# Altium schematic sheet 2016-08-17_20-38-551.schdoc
size 778 x 358 mm; SheetNumber: 1; SheetTotal: 1
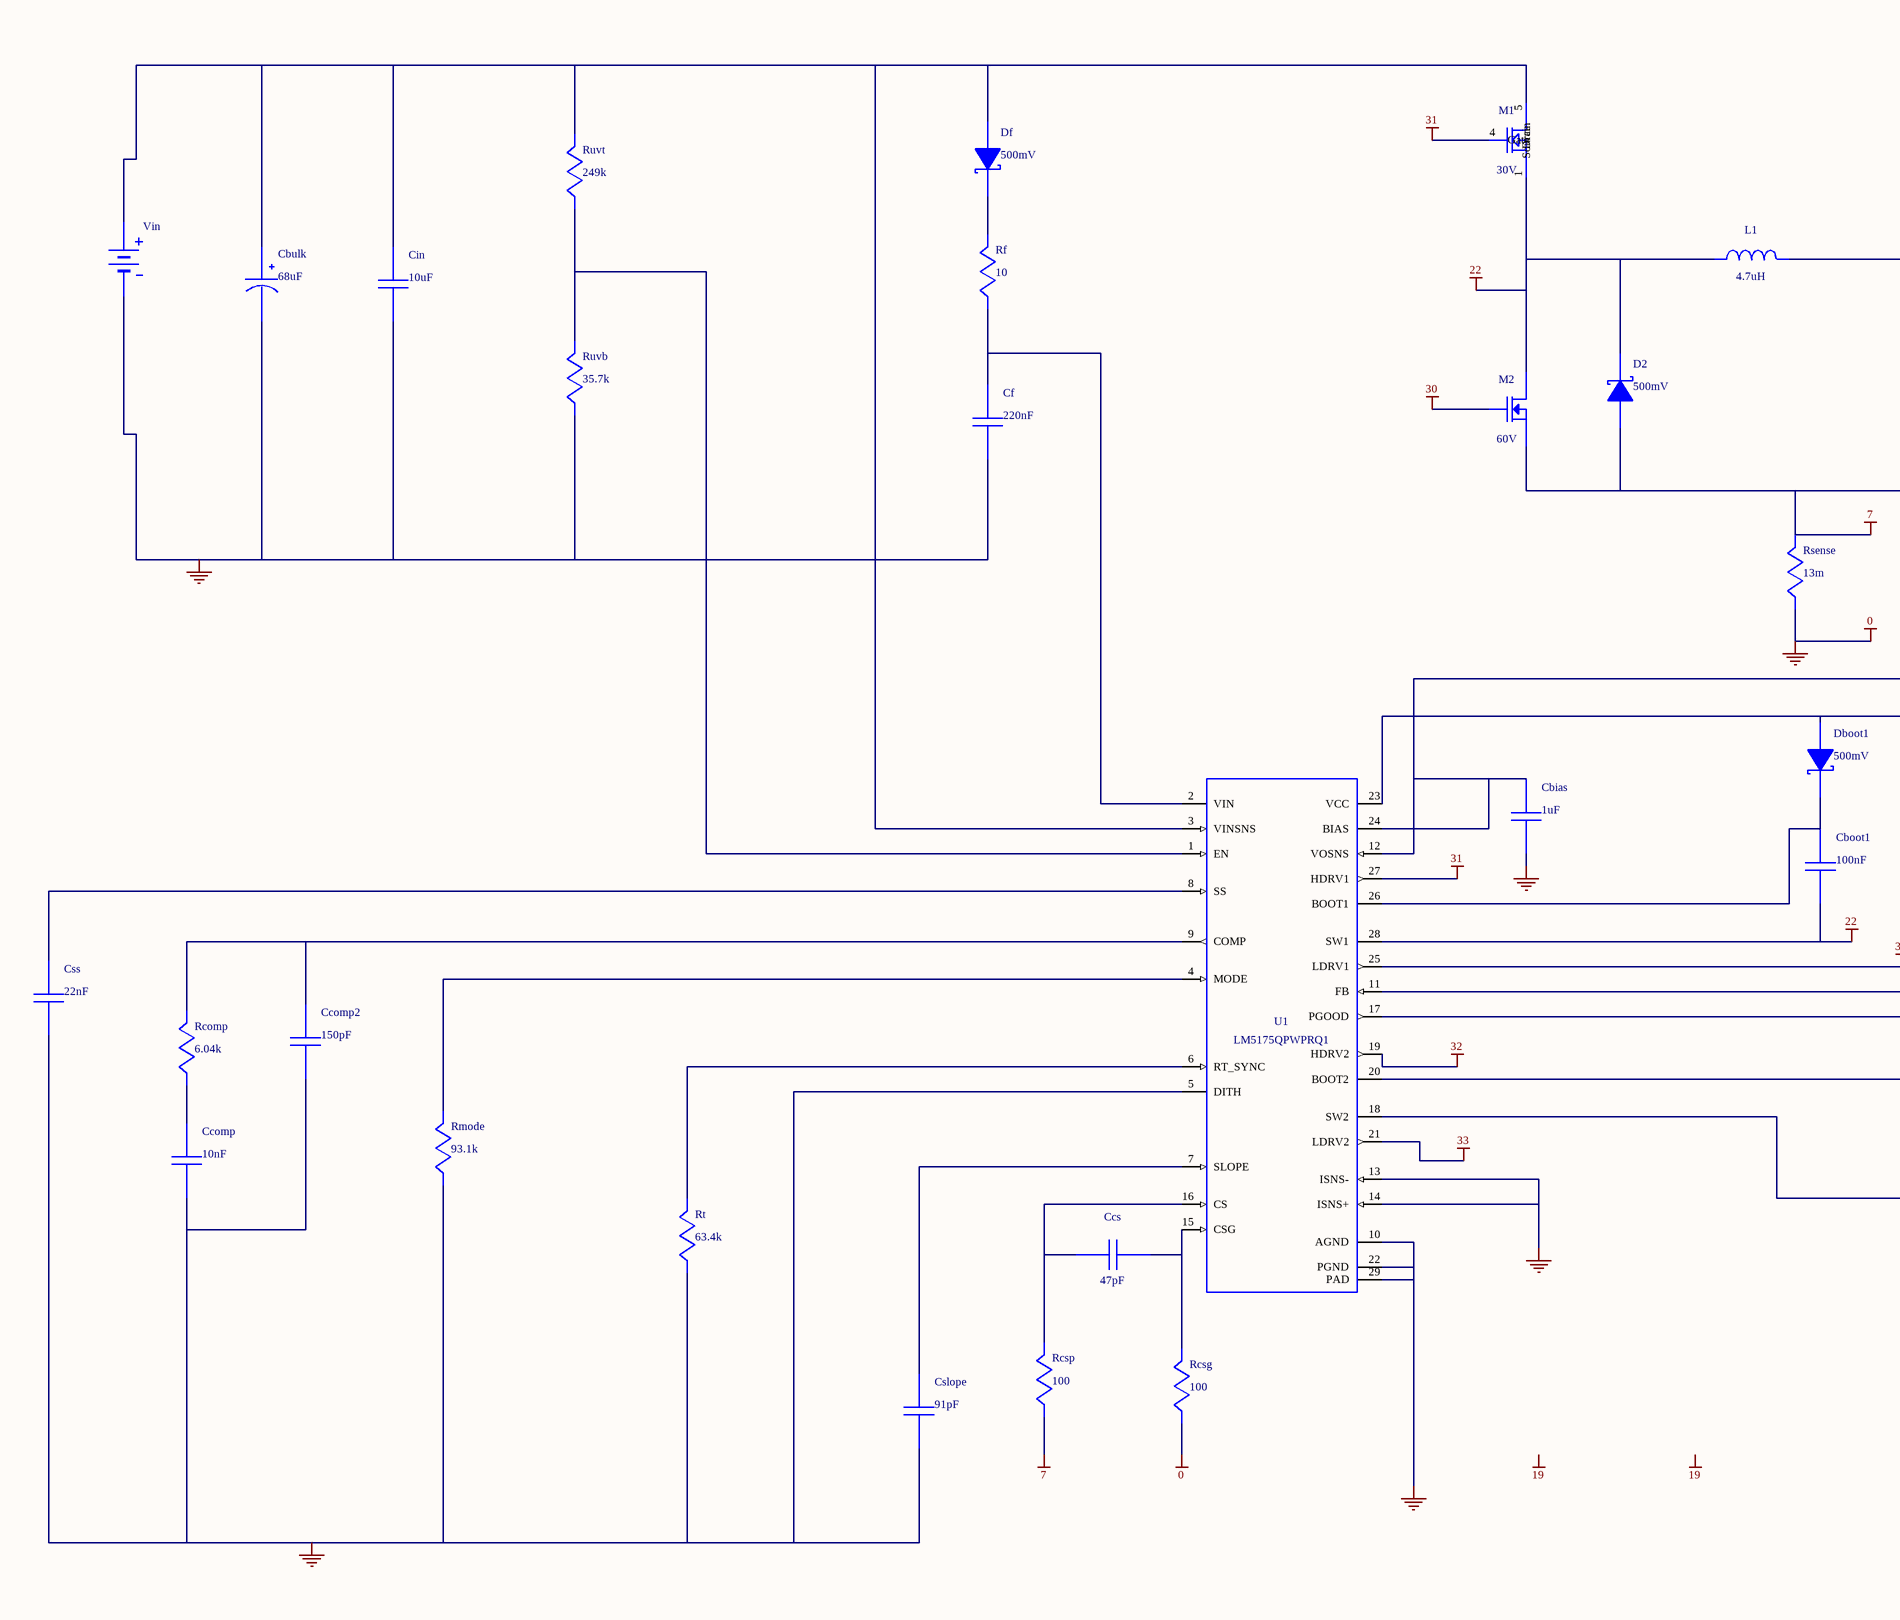
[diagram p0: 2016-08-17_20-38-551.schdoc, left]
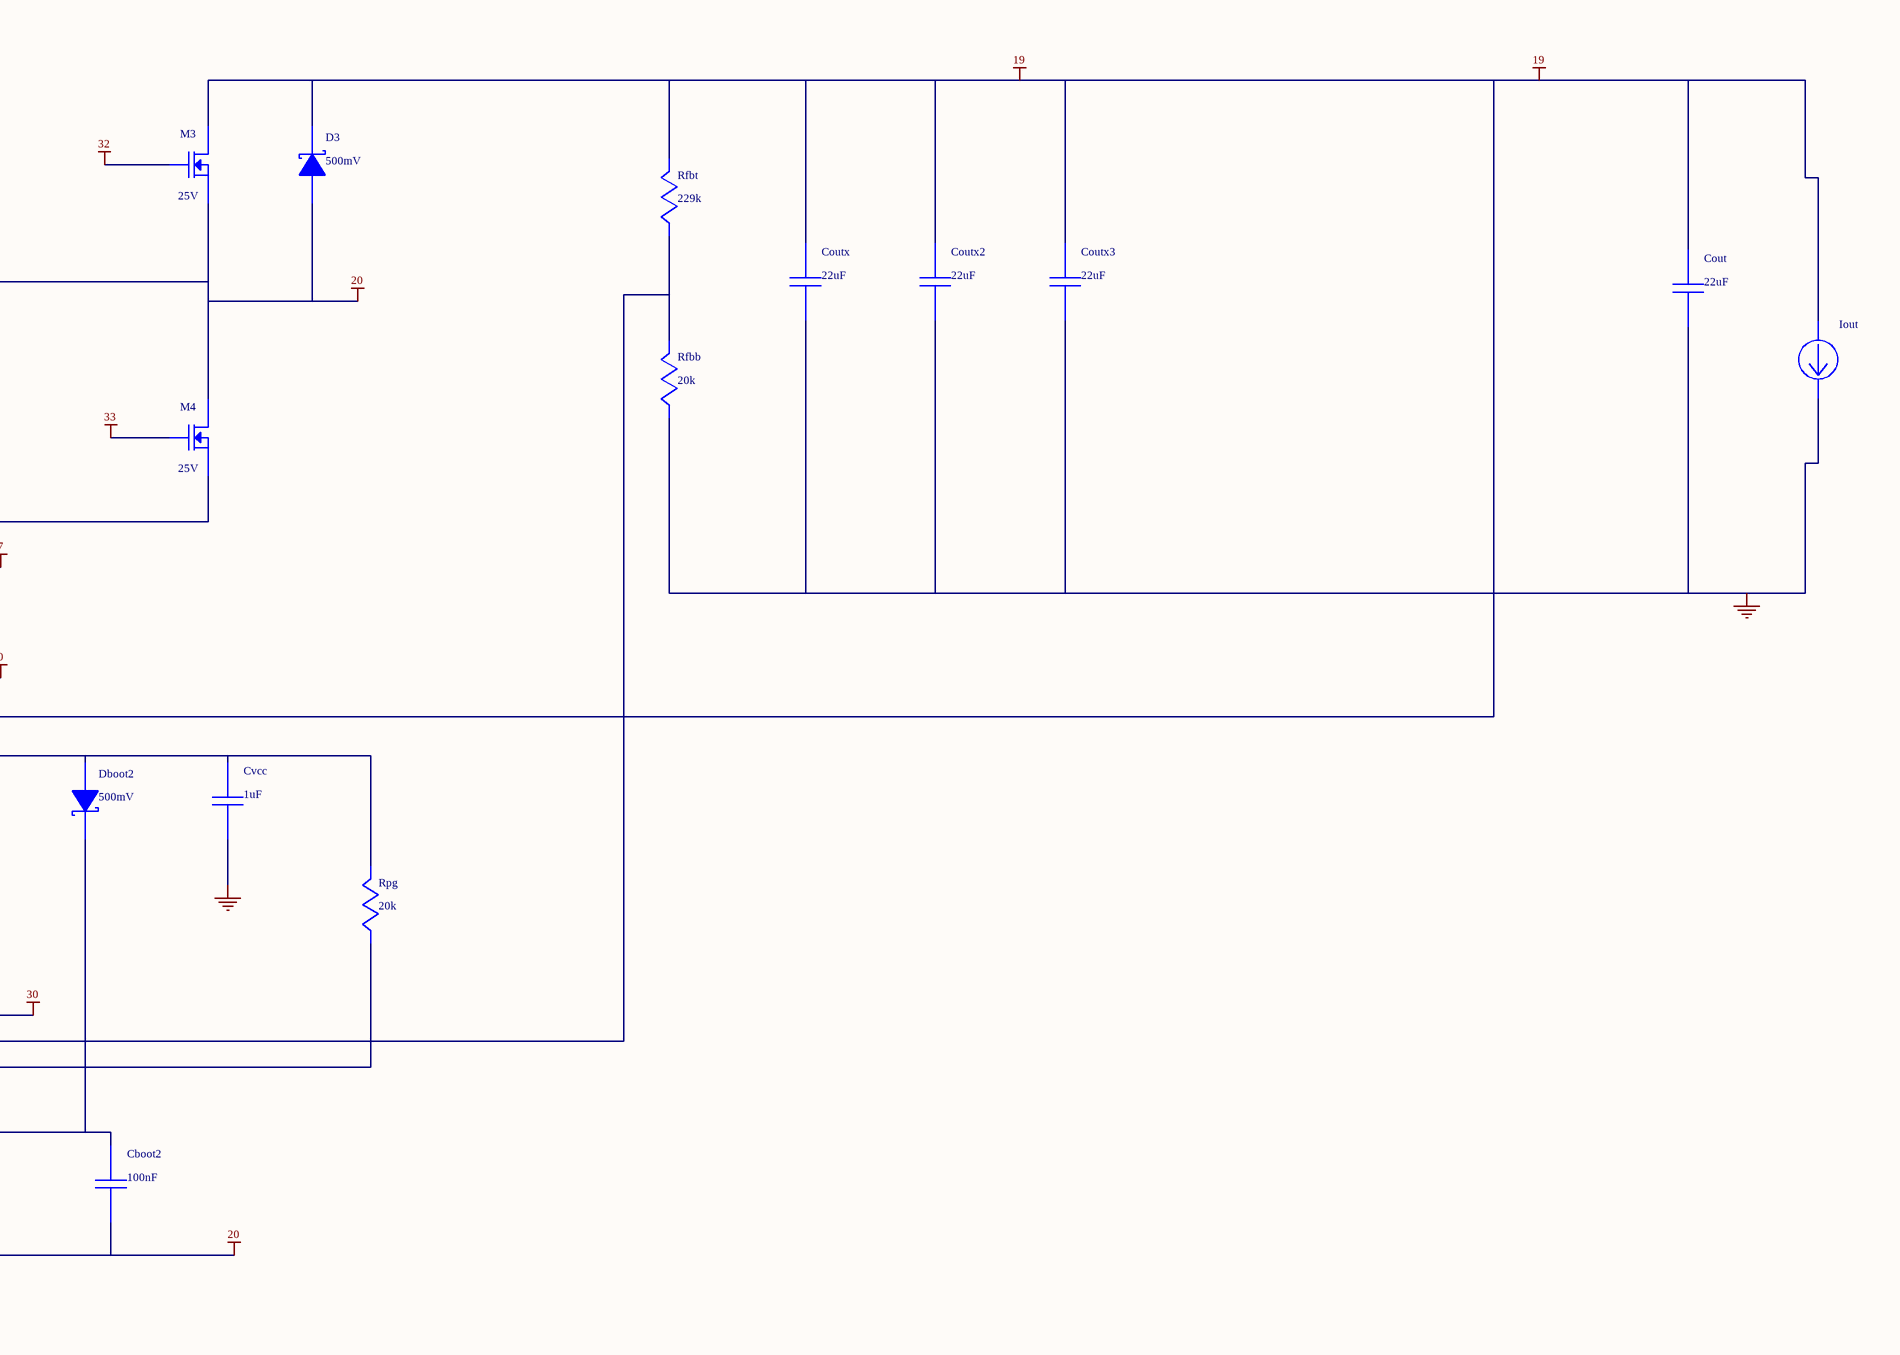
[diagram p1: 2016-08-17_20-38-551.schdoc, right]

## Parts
Cbias  value 1uF  (hidden comment: GRM188R61C105KA93D)
Cboot1  value 100nF  (hidden comment: C0603C104K3RACTU)
Cboot2  value 100nF  (hidden comment: C0603C104K3RACTU)
Cbulk  value 68uF  (hidden comment: UUD1E680MCL1GS)
Ccomp  value 10nF  (hidden comment: CC0805KRX7R9BB103)
Ccomp2  value 150pF  (hidden comment: C2012C0G1H151J)
Ccs  value 47pF  (hidden comment: 06035A470JAT2A)
Cf  value 220nF  (hidden comment: C0805C224K5RACTU)
Cin  value 10uF  (hidden comment: GRM32ER7YA106KA12L)
Cout  value 22uF  (hidden comment: GRM32ER61C226ME20L)
Coutx  value 22uF  (hidden comment: C3216JB1E226M)
Coutx2  value 22uF  (hidden comment: C3216JB1E226M)
Coutx3  value 22uF  (hidden comment: C3216JB1E226M)
Cslope  value 91pF  (hidden comment: CL10C910JB8NCNC)
Css  value 22nF  (hidden comment: C0603C223K3RACTU)
Cvcc  value 1uF  (hidden comment: GRM188R61C105KA93D)
D2  value 500mV  (hidden comment: CD214A-B130LF)
D3  value 500mV  (hidden comment: SS12-E3/61T)
Dboot1  value 500mV  (hidden comment: CD214A-B130LF)
Dboot2  value 500mV  (hidden comment: CD214A-B130LF)
Df  value 500mV  (hidden comment: CD214A-B130LF)
Iout  WB_CURRENT_LOAD  (value not drawn)
L1  value 4.7uH  (hidden comment: SDR0805-4R7ML)
M1  value 30V  (hidden comment: CSD17551Q3A)
M2  value 60V  (hidden comment: CSD18537NQ5A)
M3  value 25V  (hidden comment: CSD16323Q3)
M4  value 25V  (hidden comment: CSD16323Q3)
Rcomp  value 6.04k  (hidden comment: CRCW04026K04FKED)
Rcsg  value 100  (hidden comment: CRCW0603100RFKEA)
Rcsp  value 100  (hidden comment: CRCW0603100RFKEA)
Rf  value 10  (hidden comment: CRCW060310R0FKEA)
Rfbb  value 20k  (hidden comment: CRCW060320K0FKEA)
Rfbt  value 229k  (hidden comment: RT0805BRD07229KL)
Rmode  value 93.1k  (hidden comment: CRCW060393K1FKEA)
Rpg  value 20k  (hidden comment: CRCW060320K0FKEA)
Rsense  value 13m  (hidden comment: PRL1632-R013-F-T1)
Rt  value 63.4k  (hidden comment: CRCW040263K4FKED)
Ruvb  value 35.7k  (hidden comment: CRCW040235K7FKED)
Ruvt  value 249k  (hidden comment: CRCW0402249KFKED)
U1  LM5175QPWPRQ1
Vin  WB_BATTERY  (value not drawn)

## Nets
0: Cbias.2 Cbulk.2(-) Ccomp.2 Ccomp2.2 Cf.2 Cin.2 Cout.2 Coutx.2 Coutx2.2 Coutx3.2 Cslope.2 Css.2 Cvcc.2 Iout.2(-) Rcsg.2 Rfbb.2 Rmode.2 Rsense.2 Rt.2 Ruvb.2 U1.5(DITH) U1.10(AGND) U1.13(ISNS-) U1.14(ISNS+) U1.22(PGND) U1.29(PAD) Vin.2(-)
7: D2.2(A) M2.1(Source) M2.2(Source) M2.3(Source) M4.1(Source) M4.2(Source) M4.3(Source) Rcsp.2 Rsense.1
19: Cbias.1 Cout.1 Coutx.1 Coutx2.1 Coutx3.1 D3.1(K) Iout.1(+) M3.5(Drain) M3.6(Drain) M3.7(Drain) M3.8(Drain) M3.9(Drain) Rfbt.1 U1.12(VOSNS) U1.24(BIAS)
20: Cboot2.2 D3.2(A) L1.2 M3.1(Source) M3.2(Source) M3.3(Source) M4.5(Drain) M4.6(Drain) M4.7(Drain) M4.8(Drain) M4.9(Drain) U1.18(SW2)
22: Cboot1.2 D2.1(K) L1.1 M1.1(Source) M1.2(Source) M1.3(Source) M2.5(Drain) M2.6(Drain) M2.7(Drain) M2.8(Drain) M2.9(Drain) U1.28(SW1)
30: M2.4(Gate) U1.25(LDRV1)
31: M1.4(Gate) U1.27(HDRV1)
32: M3.4(Gate) U1.19(HDRV2)
33: M4.4(Gate) U1.21(LDRV2)
NetCboot1_1: Cboot1.1 Dboot1.1(K) U1.26(BOOT1)
NetCboot2_1: Cboot2.1 Dboot2.1(K) U1.20(BOOT2)
NetCbulk_1: Cbulk.1(+) Cin.1 Df.2(A) M1.5(Drain) M1.6(Drain) M1.7(Drain) M1.8(Drain) Ruvt.1 U1.3(VINSNS) Vin.1(+)
NetCcomp2_1: Ccomp2.1 Rcomp.1 U1.9(COMP)
NetCcomp_1: Ccomp.1 Rcomp.2
NetCcs_1: Ccs.1 Rcsp.1 U1.16(CS)
NetCcs_2: Ccs.2 Rcsg.1 U1.15(CSG)
NetCf_1: Cf.1 Rf.2 U1.2(VIN)
NetCslope_1: Cslope.1 U1.7(SLOPE)
NetCss_1: Css.1 U1.8(SS)
NetCvcc_1: Cvcc.1 Dboot1.2(A) Dboot2.2(A) Rpg.1 U1.23(VCC)
NetDf_1: Df.1(K) Rf.1
NetRfbb_1: Rfbb.1 Rfbt.2 U1.11(FB)
NetRmode_1: Rmode.1 U1.4(MODE)
NetRpg_2: Rpg.2 U1.17(PGOOD)
NetRt_1: Rt.1 U1.6(RT_SYNC)
NetRuvb_1: Ruvb.1 Ruvt.2 U1.1(EN)

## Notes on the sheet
- Labels drawn without touching a wire or pin: 19

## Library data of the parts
Cbias Cvcc = GRM188R61C105KA93D: GRM188R61C105KA9; Manufacturer Name: MuRata
Cboot1 Cboot2 = C0603C104K3RACTU: Manufacturer Name: Kemet
Cbulk = UUD1E680MCL1GS: Manufacturer Name: Nichicon
Ccomp = CC0805KRX7R9BB103: CC0805KRX7R9BB10; Manufacturer Name: Yageo America
Ccomp2 = C2012C0G1H151J: Manufacturer Name: TDK
Ccs = 06035A470JAT2A: Manufacturer Name: AVX
Cf = C0805C224K5RACTU: Manufacturer Name: Kemet
Cin = GRM32ER7YA106KA12L: GRM32ER7YA106KA1; Manufacturer Name: MuRata
Cout = GRM32ER61C226ME20L: GRM32ER61C226ME2; Manufacturer Name: MuRata
Coutx Coutx2 Coutx3 = C3216JB1E226M: Manufacturer Name: TDK
Cslope = CL10C910JB8NCNC: Manufacturer Name: Samsung Electro-Mechanics
Css = C0603C223K3RACTU: Manufacturer Name: Kemet
D2 Dboot1 Dboot2 Df = CD214A-B130LF: Manufacturer Name: Bourns
D3 = SS12-E3/61T: Manufacturer Name: Vishay-Semiconductor
L1 = SDR0805-4R7ML: Manufacturer Name: Bourns
M1 = CSD17551Q3A: Manufacturer Name: Texas Instruments
M2 = CSD18537NQ5A: Manufacturer Name: Texas Instruments
M3 M4 = CSD16323Q3: Manufacturer Name: Texas Instruments
Rcomp = CRCW04026K04FKED: Manufacturer Name: Vishay-Dale
Rcsg Rcsp = CRCW0603100RFKEA: Manufacturer Name: Vishay-Dale
Rf = CRCW060310R0FKEA: Manufacturer Name: Vishay-Dale
Rfbb Rpg = CRCW060320K0FKEA: Manufacturer Name: Vishay-Dale
Rfbt = RT0805BRD07229KL: Manufacturer Name: Yageo America
Rmode = CRCW060393K1FKEA: Manufacturer Name: Vishay-Dale
Rsense = PRL1632-R013-F-T1: PRL1632-R013-F-T; Manufacturer Name: Susumu Co Ltd
Rt = CRCW040263K4FKED: Manufacturer Name: Vishay-Dale
Ruvb = CRCW040235K7FKED: Manufacturer Name: Vishay-Dale
Ruvt = CRCW0402249KFKED: Manufacturer Name: Vishay-Dale
U1 = LM5175QPWPRQ1: Manufacturer Name: Texas Instruments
